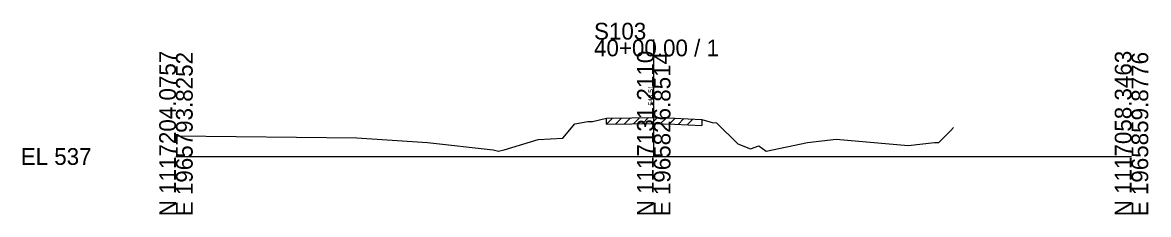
# Model space of a CAD drawing. Extents: x -26 to 163, y -10 to 45020.
# Drawn here: x -25.7 to 162.8, y -9.7 to 22.4 of the extents above; entities that cross this region are included whole.
import ezdxf

# ---------------------------------------------------------------- set-up
doc = ezdxf.new("R2010")
doc.units = 0
for name, color, linetype in [('RD_GPK_XS_Cell', 7, 'Continuous'), ('RD_XS_ExGround', 7, 'Continuous'), ('RD_XS_ExPaveRet', 7, 'Continuous'), ('RD_XS_TX_Elev_EX', 7, 'Continuous')]:
    doc.layers.add(name, color=color, linetype=linetype)

msp = doc.modelspace()

# ---------------------------------------------------------------- linework, layer by layer
at = {"layer": 'RD_GPK_XS_Cell'}
for p, q in [((80, 0), (80, 19.56)), ((0, 0), (80, 0)), ((80, 0), (160, 0))]:
    msp.add_line(p, q, dxfattribs=at)
at = {"layer": 'RD_XS_ExGround'}
for p, q in [((66.8, 5.46), (68.99, 5.84)), ((68.99, 5.84), (69.74, 5.87)), ((69.74, 5.87), (72.1, 6.41)), ((72.1, 6.41), (76.31, 6.46)), ((76.31, 6.46), (79.76, 6.52)), ((79.76, 6.52), (83.46, 6.4)), ((83.46, 6.4), (88.04, 6.2)), ((88.04, 6.2), (89.76, 5.68)), ((89.76, 5.68), (90.53, 5.62)), ((64.78, 3.07), (66.8, 5.46)), ((90.53, 5.62), (94.1, 2.11)), ((127.74, 2.35), (129.77, 4.35)), ((129.77, 4.35), (130.2, 4.84)), ((0, 3.45), (30.3, 3.14)), ((30.3, 3.14), (42.1, 2.32)), ((42.1, 2.32), (53.09, 1.14)), ((54.96, 1.12), (60.65, 2.83)), ((60.65, 2.83), (64.78, 3.07)), ((94.1, 2.11), (96.21, 1.29)), ((98.81, 0.91), (105.77, 2.37)), ((105.77, 2.37), (110.52, 2.92)), ((110.52, 2.92), (122.59, 1.83)), ((122.59, 1.83), (127, 2.34)), ((127, 2.34), (127.74, 2.35)), ((53.09, 1.14), (53.99, 0.87)), ((53.99, 0.87), (54.96, 1.12)), ((96.21, 1.29), (97.58, 1.81)), ((97.58, 1.81), (98.81, 0.91))]:
    msp.add_line(p, q, dxfattribs=at)
at = {"layer": 'RD_XS_ExPaveRet'}
for p, q in [((72.1, 5.41), (73.11, 6.42)), ((72.1, 5.41), (72.1, 6.41)), ((73.6, 5.43), (74.61, 6.44)), ((75.1, 5.45), (76.11, 6.46)), ((76.6, 5.47), (77.62, 6.48)), ((78.1, 5.49), (79.12, 6.51)), ((79.6, 5.52), (80.57, 6.49)), ((81.1, 5.48), (82.07, 6.44)), ((82.6, 5.42), (83.57, 6.39)), ((84.1, 5.37), (85.06, 6.33)), ((85.6, 5.3), (86.56, 6.26)), ((88.04, 6.2), (88.04, 5.2)), ((72.1, 5.41), (76.31, 5.46)), ((76.31, 5.46), (79.76, 5.52)), ((79.76, 5.52), (83.46, 5.4)), ((83.46, 5.4), (88.04, 5.2))]:
    msp.add_line(p, q, dxfattribs=at)

# ---------------------------------------------------------------- texts
at = {"layer": 'RD_GPK_XS_Cell'}
for s, p in [('S103', (70, 19.56)), ('40+00.00 / 1', (70, 16.76)), ('EL 537', (-26, -1.4))]:
    msp.add_text(s, height=2.8, dxfattribs=at).set_placement(p)
for s, p in [('N 1117204.0757', (0, -10)), ('E 1965793.8252', (2.8, -10)), ('N 1117131.2110', (80, -10)), ('E 1965826.8514', (82.8, -10)), ('N 1117058.3463', (160, -10)), ('E 1965859.8776', (162.8, -10))]:
    msp.add_text(s, height=2.8, rotation=90, dxfattribs=at).set_placement(p)
at = {"layer": 'RD_XS_TX_Elev_EX'}
msp.add_text('543.51', height=0.8, rotation=90, dxfattribs=at).set_placement((79.9, 8.51))

doc.saveas('drawing.dxf')
